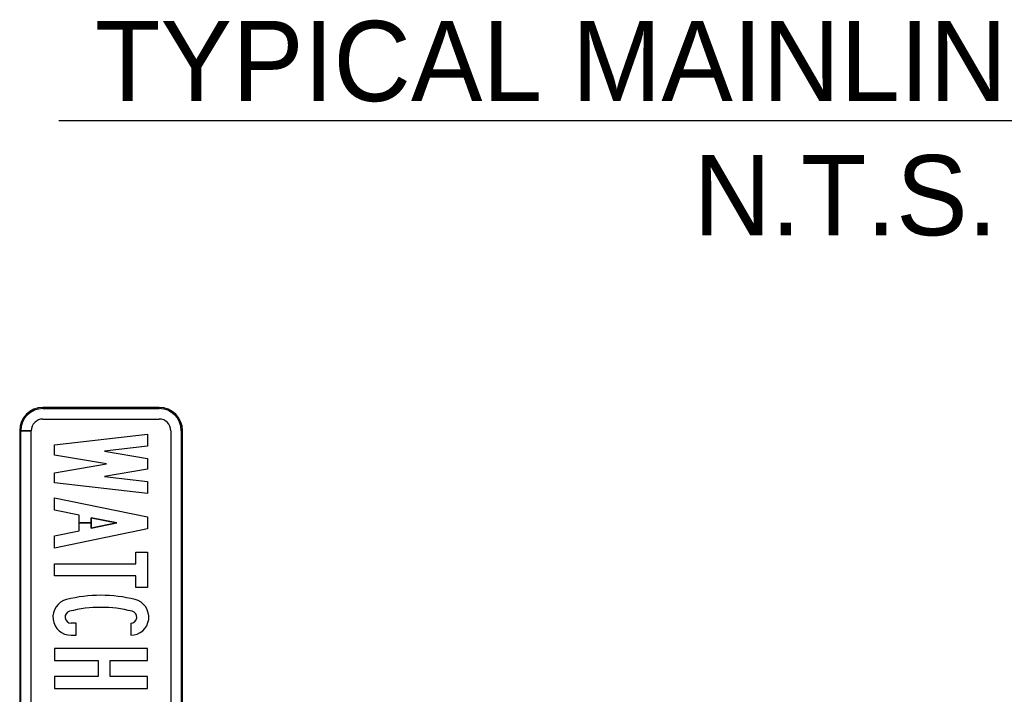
# Model space of a CAD drawing. Extents: x 524708 to 525490, y 1531861 to 1532506.
# Drawn here: x 525097.4 to 525153.9, y 1532140 to 1532178.6 of the extents above; entities that cross this region are included whole.
import ezdxf

# ---------------------------------------------------------------- set-up
doc = ezdxf.new("R2010")
doc.units = 0
for name, color, linetype in [('GSBWFill', 7, 'Continuous'), ('GSColorFill', 7, 'Continuous'), ('GSOutline', 7, 'Continuous'), ('TextDetails', 7, 'Continuous')]:
    doc.layers.add(name, color=color, linetype=linetype)

msp = doc.modelspace()

# ---------------------------------------------------------------- linework, layer by layer
at = {"layer": 'GSBWFill'}
for p, q in [((525100.645, 1532144.034), (525100.352, 1532144.034)), ((525103.773, 1532144.034), (525103.773, 1532143.341))]:
    msp.add_line(p, q, dxfattribs=at)
for points in [[(525102.391, 1532153.167), (525099.405, 1532153.674), (525099.405, 1532154.261), (525104.738, 1532154.874), (525104.738, 1532154.176), (525102.266, 1532153.892), (525104.738, 1532153.473), (525104.738, 1532152.862), (525102.266, 1532152.443), (525104.738, 1532152.159), (525104.738, 1532151.461), (525099.405, 1532152.074), (525099.405, 1532152.661)], [(525101.511, 1532149.781), (525101.511, 1532149.48), (525102.977, 1532149.781), (525101.511, 1532150.081), (525101.511, 1532149.781), (525100.818, 1532149.781), (525100.818, 1532150.223), (525099.405, 1532150.513), (525099.405, 1532151.221), (525104.738, 1532150.127), (525104.738, 1532149.434), (525099.405, 1532148.341), (525099.405, 1532149.049), (525100.818, 1532149.338), (525100.818, 1532149.781)], [(525104.071, 1532146.074), (525104.071, 1532146.741), (525099.405, 1532146.741), (525099.405, 1532147.434), (525104.071, 1532147.434), (525104.071, 1532148.101), (525104.738, 1532148.101), (525104.738, 1532146.074)], [(525099.405, 1532142.581), (525099.405, 1532141.888), (525101.911, 1532141.888), (525101.911, 1532140.981), (525099.405, 1532140.981), (525099.405, 1532140.288), (525104.738, 1532140.288), (525104.738, 1532140.981), (525102.605, 1532140.981), (525102.605, 1532141.888), (525104.738, 1532141.888), (525104.738, 1532142.581)]]:
    msp.add_lwpolyline(points, close=True, dxfattribs=at)
msp.add_lwpolyline([(525100.352, 1532143.341), (525100.645, 1532143.341), (525100.645, 1532144.034)], dxfattribs=at)
for centre, major_axis, start_param, end_param in [((525102.062, 1532137.629), (8.005, 0), 1.322662, 1.818931), ((525100.352, 1532144.381), (1.04, 0), 1.818931, 4.712389), ((525102.062, 1532137.629), (7.312, 0), 1.322662, 1.818931), ((525103.773, 1532144.381), (1.04, 0), 4.712389, 7.605847), ((525100.352, 1532144.381), (0.347, 0), 1.818931, 4.712389), ((525103.773, 1532144.381), (0.347, 0), 4.712389, 7.605847)]:
    msp.add_ellipse(centre, major_axis=major_axis, ratio=0.999994, start_param=start_param, end_param=end_param, dxfattribs=at)
at = {"layer": 'GSColorFill'}
for p, q in [((525105.409, 1532156.406), (525098.742, 1532156.406)), ((525105.409, 1532156.406), (525098.742, 1532156.406)), ((525105.409, 1532156.406), (525098.742, 1532156.406)), ((525098.742, 1532156.339), (525105.409, 1532156.339)), ((525098.742, 1532155.739), (525105.409, 1532155.739)), ((525097.409, 1532155.072), (525098.076, 1532155.072)), ((525097.409, 1532155.072), (525097.409, 1532092.406)), ((525097.409, 1532155.072), (525097.476, 1532155.072)), ((525097.476, 1532155.072), (525097.409, 1532155.072)), ((525097.409, 1532155.072), (525097.409, 1532092.406)), ((525097.409, 1532155.066), (525097.409, 1532092.406)), ((525098.076, 1532155.066), (525097.409, 1532155.066)), ((525097.476, 1532092.406), (525097.476, 1532155.072)), ((525098.076, 1532092.406), (525098.076, 1532155.066)), ((525106.076, 1532155.072), (525106.076, 1532092.406)), ((525106.676, 1532155.072), (525106.676, 1532092.406)), ((525106.742, 1532092.406), (525106.742, 1532155.072)), ((525106.742, 1532092.406), (525106.742, 1532155.072)), ((525106.742, 1532092.406), (525106.742, 1532155.072)), ((525100.645, 1532144.034), (525100.352, 1532144.034)), ((525103.773, 1532144.034), (525103.773, 1532143.341))]:
    msp.add_line(p, q, dxfattribs=at)
for points in [[(525102.391, 1532153.167), (525099.405, 1532153.674), (525099.405, 1532154.261), (525104.738, 1532154.874), (525104.738, 1532154.176), (525102.266, 1532153.892), (525104.738, 1532153.473), (525104.738, 1532152.862), (525102.266, 1532152.443), (525104.738, 1532152.159), (525104.738, 1532151.461), (525099.405, 1532152.074), (525099.405, 1532152.661)], [(525101.511, 1532149.781), (525101.511, 1532149.48), (525102.977, 1532149.781), (525101.511, 1532150.081), (525101.511, 1532149.781), (525100.818, 1532149.781), (525100.818, 1532150.223), (525099.405, 1532150.513), (525099.405, 1532151.221), (525104.738, 1532150.127), (525104.738, 1532149.434), (525099.405, 1532148.341), (525099.405, 1532149.049), (525100.818, 1532149.338), (525100.818, 1532149.781)], [(525104.071, 1532146.074), (525104.071, 1532146.741), (525099.405, 1532146.741), (525099.405, 1532147.434), (525104.071, 1532147.434), (525104.071, 1532148.101), (525104.738, 1532148.101), (525104.738, 1532146.074)], [(525099.405, 1532142.581), (525099.405, 1532141.888), (525101.911, 1532141.888), (525101.911, 1532140.981), (525099.405, 1532140.981), (525099.405, 1532140.288), (525104.738, 1532140.288), (525104.738, 1532140.981), (525102.605, 1532140.981), (525102.605, 1532141.888), (525104.738, 1532141.888), (525104.738, 1532142.581)]]:
    msp.add_lwpolyline(points, close=True, dxfattribs=at)
msp.add_lwpolyline([(525100.352, 1532143.341), (525100.645, 1532143.341), (525100.645, 1532144.034)], dxfattribs=at)
for centre, radius, start, end in [((525098.742, 1532155.072), 1.333, 90, 180), ((525098.742, 1532155.072), 1.333, 90, 180), ((525098.742, 1532155.072), 1.333, 90, 180), ((525098.742, 1532155.072), 1.267, 90, 180), ((525105.409, 1532155.072), 1.333, 0, 90), ((525105.409, 1532155.072), 1.333, 0, 90), ((525105.409, 1532155.072), 1.333, 0, 90), ((525105.409, 1532155.072), 1.267, 0, 90), ((525098.742, 1532155.072), 0.667, 90, 180), ((525105.409, 1532155.072), 0.667, 0, 90)]:
    msp.add_arc(centre, radius, start, end, dxfattribs=at)
for centre, major_axis, start_param, end_param in [((525102.062, 1532137.629), (8.005, 0), 1.322662, 1.818931), ((525100.352, 1532144.381), (1.04, 0), 1.818931, 4.712389), ((525102.062, 1532137.629), (7.312, 0), 1.322662, 1.818931), ((525103.773, 1532144.381), (1.04, 0), 4.712389, 7.605847), ((525100.352, 1532144.381), (0.347, 0), 1.818931, 4.712389), ((525103.773, 1532144.381), (0.347, 0), 4.712389, 7.605847)]:
    msp.add_ellipse(centre, major_axis=major_axis, ratio=0.999994, start_param=start_param, end_param=end_param, dxfattribs=at)
at = {"layer": 'GSOutline'}
for p, q in [((525100.645, 1532144.034), (525100.352, 1532144.034)), ((525103.773, 1532144.034), (525103.773, 1532143.341))]:
    msp.add_line(p, q, dxfattribs=at)
for points in [[(525102.391, 1532153.167), (525099.405, 1532153.674), (525099.405, 1532154.261), (525104.738, 1532154.874), (525104.738, 1532154.176), (525102.266, 1532153.892), (525104.738, 1532153.473), (525104.738, 1532152.862), (525102.266, 1532152.443), (525104.738, 1532152.159), (525104.738, 1532151.461), (525099.405, 1532152.074), (525099.405, 1532152.661)], [(525099.405, 1532150.513), (525099.405, 1532151.221), (525104.738, 1532150.127), (525104.738, 1532149.434), (525099.405, 1532148.341), (525099.405, 1532149.049), (525100.818, 1532149.338), (525100.818, 1532150.223)], [(525101.511, 1532149.48), (525101.511, 1532150.081), (525102.977, 1532149.781)], [(525104.071, 1532146.074), (525104.071, 1532146.741), (525099.405, 1532146.741), (525099.405, 1532147.434), (525104.071, 1532147.434), (525104.071, 1532148.101), (525104.738, 1532148.101), (525104.738, 1532146.074)], [(525099.405, 1532142.581), (525099.405, 1532141.888), (525101.911, 1532141.888), (525101.911, 1532140.981), (525099.405, 1532140.981), (525099.405, 1532140.288), (525104.738, 1532140.288), (525104.738, 1532140.981), (525102.605, 1532140.981), (525102.605, 1532141.888), (525104.738, 1532141.888), (525104.738, 1532142.581)]]:
    msp.add_lwpolyline(points, close=True, dxfattribs=at)
msp.add_lwpolyline([(525100.352, 1532143.341), (525100.645, 1532143.341), (525100.645, 1532144.034)], dxfattribs=at)
for centre, major_axis, start_param, end_param in [((525102.062, 1532137.629), (8.005, 0), 1.322662, 1.818931), ((525100.352, 1532144.381), (1.04, 0), 1.818931, 4.712389), ((525102.062, 1532137.629), (7.312, 0), 1.322662, 1.818931), ((525103.773, 1532144.381), (1.04, 0), 4.712389, 7.605847), ((525100.352, 1532144.381), (0.347, 0), 1.818931, 4.712389), ((525103.773, 1532144.381), (0.347, 0), 4.712389, 7.605847)]:
    msp.add_ellipse(centre, major_axis=major_axis, ratio=0.999994, start_param=start_param, end_param=end_param, dxfattribs=at)
at = {"layer": 'TextDetails'}
msp.add_line((525099.656, 1532172.851), (525192.614, 1532172.852), dxfattribs=at)

# ---------------------------------------------------------------- texts
for s, height, p in [('TYPICAL MAINLINE PLAZA', 4.59999, (525101.723, 1532173.971)), ('N.T.S.', 4.6, (525136.039, 1532166.277))]:
    msp.add_text(s, height=height, rotation=0.0001, dxfattribs=at).set_placement(p)

doc.saveas('drawing.dxf')
